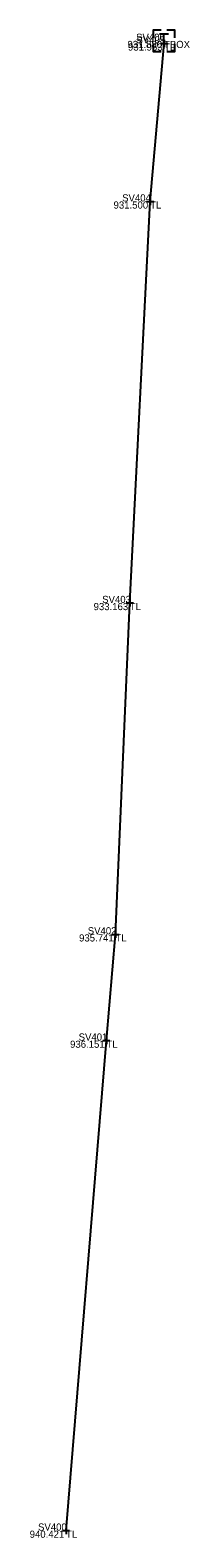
# Model space of a CAD drawing. Extents: x 1988962 to 1988984, y 658619 to 658830.
import ezdxf

# ---------------------------------------------------------------- set-up
doc = ezdxf.new("R2010")
doc.units = 0
for name, color, linetype in [('SV_P_Aerial_Targets', 7, 'Continuous'), ('SV_X_Text_Comment', 7, 'Continuous'), ('SV_X_Text_Elevation', 7, 'Continuous'), ('SV_X_Text_Name', 7, 'Continuous'), ('TopoDOT Temp', 7, 'Continuous'), ('TopoDOT_Transients', 7, 'Continuous')]:
    doc.layers.add(name, color=color, linetype=linetype)

msp = doc.modelspace()

# ---------------------------------------------------------------- linework, layer by layer
at = {"layer": 'SV_X_Text_Comment'}
msp.add_lwpolyline([(1988967.08, 658620.12), (1988972.73, 658688.59), (1988973.99, 658703.44), (1988976, 658749.74), (1988978.85, 658805.85), (1988980.81, 658827.93)], dxfattribs=at)
at = {"layer": 'SV_X_Text_Elevation'}
for p, q in [((1988980.14, 658829.29), (1988981.43, 658829.29)), ((1988980.78, 658827.29), (1988980.78, 658829.29)), ((1988980.78, 658828.29), (1988980.78, 658828.29))]:
    msp.add_line(p, q, dxfattribs=at)
for points in [[(1988980.39, 658829.79), (1988979.28, 658829.79), (1988979.28, 658828.69)], [(1988982.28, 658828.69), (1988982.28, 658829.79), (1988981.18, 658829.79)], [(1988979.28, 658827.89), (1988979.28, 658826.79), (1988980.39, 658826.79)], [(1988981.18, 658826.79), (1988982.28, 658826.79), (1988982.28, 658827.89)]]:
    msp.add_lwpolyline(points, dxfattribs=at)
at = {"layer": 'TopoDOT_Transients'}
for p, q in [((1988980.31, 658827.93), (1988981.31, 658827.93)), ((1988980.81, 658828.43), (1988980.81, 658827.43)), ((1988980.81, 658827.93), (1988980.81, 658827.93)), ((1988978.85, 658806.35), (1988978.85, 658805.35)), ((1988978.35, 658805.85), (1988979.35, 658805.85)), ((1988978.85, 658805.85), (1988978.85, 658805.85)), ((1988975.5, 658749.74), (1988976.5, 658749.74)), ((1988976, 658750.24), (1988976, 658749.24)), ((1988976, 658749.74), (1988976, 658749.74)), ((1988973.49, 658703.44), (1988974.49, 658703.44)), ((1988973.99, 658703.94), (1988973.99, 658702.94)), ((1988973.99, 658703.44), (1988973.99, 658703.44)), ((1988972.23, 658688.59), (1988973.23, 658688.59)), ((1988972.73, 658689.09), (1988972.73, 658688.09)), ((1988972.73, 658688.59), (1988972.73, 658688.59)), ((1988967.08, 658620.62), (1988967.08, 658619.62)), ((1988966.58, 658620.12), (1988967.58, 658620.12)), ((1988967.08, 658620.12), (1988967.08, 658620.12))]:
    msp.add_line(p, q, dxfattribs=at)

# ---------------------------------------------------------------- texts
at = {"layer": 'SV_P_Aerial_Targets'}
for s, p in [('931.880', (1988975.67, 658827.29)), ('931.953', (1988975.75, 658826.93)), ('931.500', (1988973.73, 658804.85)), ('933.163', (1988970.94, 658748.74)), ('935.741', (1988968.91, 658702.44)), ('936.151', (1988967.65, 658687.59)), ('940.421', (1988962, 658619.12))]:
    msp.add_text(s, height=1, dxfattribs=at).set_placement(p)
at = {"layer": 'SV_X_Text_Name'}
for s, p in [('TBOX', (1988980.78, 658827.29)), ('TL', (1988980.81, 658826.93)), ('TL', (1988978.85, 658804.85)), ('TL', (1988976, 658748.74)), ('TL', (1988973.99, 658702.44)), ('TL', (1988972.73, 658687.59)), ('TL', (1988967.08, 658619.12))]:
    msp.add_text(s, height=1, dxfattribs=at).set_placement(p)
at = {"layer": 'TopoDOT Temp'}
for s, p in [('SV406', (1988976.88, 658828.29)), ('SV405', (1988976.94, 658827.93)), ('SV404', (1988974.93, 658805.85)), ('SV403', (1988972.14, 658749.74)), ('SV402', (1988970.12, 658703.44)), ('SV401', (1988968.85, 658688.59)), ('SV400', (1988963.17, 658620.12))]:
    msp.add_text(s, height=1, dxfattribs=at).set_placement(p)

doc.saveas('drawing.dxf')
